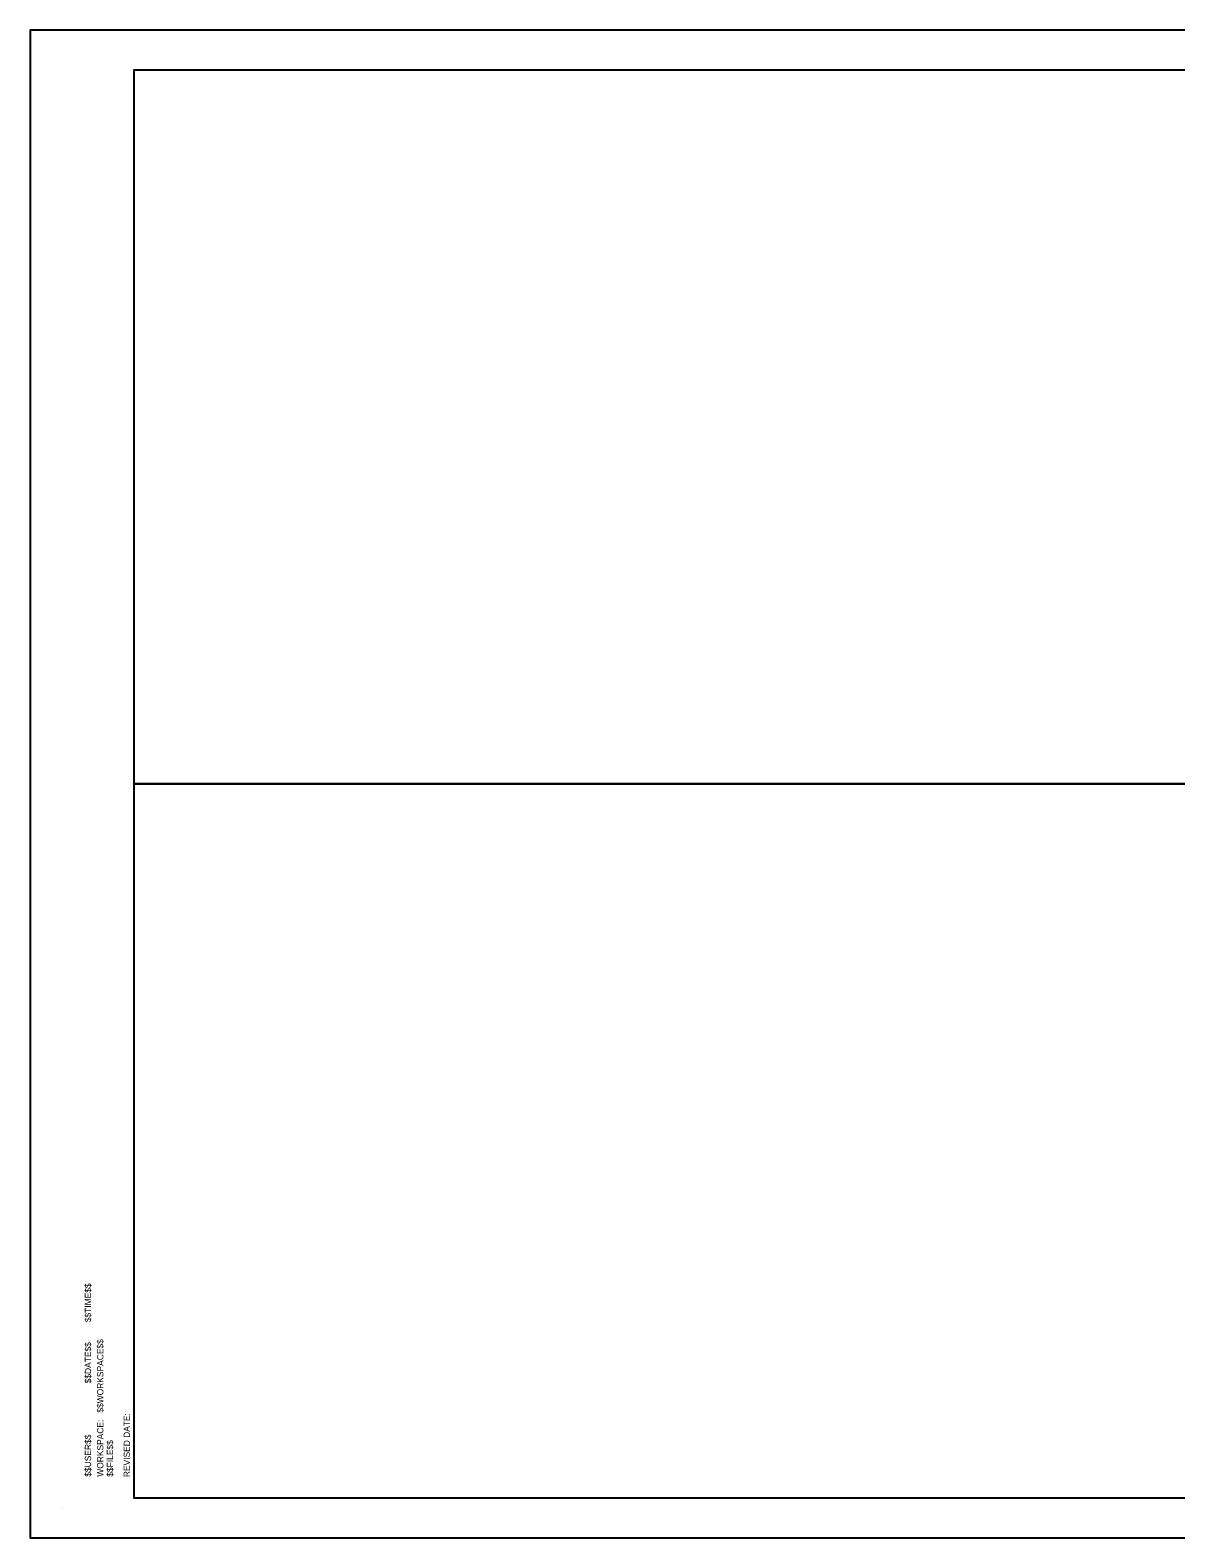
# Model space of a CAD drawing. Extents: x 1448008.9 to 1448042.9, y 2057057.8 to 2057079.8.
# Drawn here: x 1448008.95 to 1448025.66, y 2057057.82 to 2057079.82 of the extents above; entities that cross this region are included whole.
import ezdxf

# ---------------------------------------------------------------- set-up
doc = ezdxf.new("R2010")
doc.units = 0
for name, color, linetype in [('1', 7, 'Continuous'), ('G-ANNO-TEXT', 7, 'Continuous'), ('G-Border-Sheet', 7, 'Continuous'), ('G-No Plot-Border-1', 7, 'Continuous'), ('G-No Plot-Border-2', 7, 'Continuous')]:
    doc.layers.add(name, color=color, linetype=linetype)

msp = doc.modelspace()

# ---------------------------------------------------------------- linework, layer by layer
at = {"layer": '1'}
msp.add_lwpolyline([(1448042.945, 2057079.818), (1448008.945, 2057079.818), (1448008.945, 2057057.818), (1448042.945, 2057057.818)], close=True, dxfattribs=at)
at = {"layer": 'G-ANNO-TEXT'}
msp.add_line((1448009.414, 2057058.246), (1448009.414, 2057058.246), dxfattribs=at)
at = {"layer": 'G-Border-Sheet'}
for p, q in [((1448010.461, 2057079.241), (1448042.369, 2057079.241)), ((1448010.461, 2057068.818), (1448010.461, 2057079.241))]:
    msp.add_line(p, q, dxfattribs=at)
msp.add_lwpolyline([(1448010.461, 2057068.818), (1448042.369, 2057068.818), (1448042.369, 2057058.395), (1448010.461, 2057058.395)], close=True, dxfattribs=at)
at = {"layer": 'G-No Plot-Border-1'}
msp.add_lwpolyline([(1448010.461, 2057068.818), (1448010.461, 2057079.241), (1448036.402, 2057079.241), (1448036.402, 2057078.25), (1448038.387, 2057078.25), (1448038.55, 2057078.25), (1448039.819, 2057078.25), (1448039.819, 2057075.3), (1448042.369, 2057075.3), (1448042.369, 2057068.818)], close=True, dxfattribs=at)
at = {"layer": 'G-No Plot-Border-2'}
msp.add_lwpolyline([(1448010.461, 2057068.818), (1448010.461, 2057079.241), (1448033.702, 2057079.241), (1448033.702, 2057076.291), (1448036.402, 2057076.291), (1448036.402, 2057078.25), (1448038.387, 2057078.25), (1448038.797, 2057078.25), (1448042.369, 2057078.25), (1448042.369, 2057068.818)], close=True, dxfattribs=at)

# ---------------------------------------------------------------- texts
at = {"layer": 'G-ANNO-TEXT'}
for s, p in [('$$TIME$$', (1448009.835, 2057060.965)), ('$$DATE$$', (1448009.835, 2057060.072)), ('$$WORKSPACE$$', (1448010.014, 2057059.645)), ('REVISED DATE:', (1448010.401, 2057058.704)), ('WORKSPACE:', (1448010.014, 2057058.71)), ('$$USER$$', (1448009.835, 2057058.71)), ('$$FILE$$', (1448010.156, 2057058.71))]:
    msp.add_text(s, height=0.0918, rotation=90, dxfattribs=at).set_placement(p)

doc.saveas('drawing.dxf')
